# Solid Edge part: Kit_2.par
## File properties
Author: ahadarics
Last saved by: psaghy
Revision: 78
Sűrűség: 0,000 kg/m^3
Pontosság: 0,990
Username: ahadarics
Dokumentum tartalom típus: 0
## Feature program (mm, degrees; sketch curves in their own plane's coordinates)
base feature "unnamed BaseFeature 1"
sketch for "Furat_2" plane through (0, -3.875, 7) normal (0, 0, 1) x-axis (0, 1, 0)
  hole centre (-0.625, 0) bore radius 2.067
hole "Furat_2" nominal diameter 5 finite  ThreadDepth = 4.5 mm
sketch for "Kihúzás_1" #1 plane through (0, 12.5, 0) normal (0, 1, 0) x-axis (0, 0, -1)
  arc centre (0, 0) radius 6 from (4.4721, -4) to (-4.4721, -4) cw
  line (-4.4721, -4) -> (4.4721, -4)
sketch for "Kihúzás_1" #2 plane through (0, 12.5, 0) normal (0, 1, 0) x-axis (0, 0, -1)
  line (-4.4721, 4) -> (4.4721, 4)
extrude "Kihúzás_1" add finite 8.92 along -normal
thread "unnamed Thread 1"
chamfer "Letörés_1" setback 1
sketch for "Kivágás_1" #1 plane through (0, 12.5, 0) normal (0, 1, 0) x-axis (0, 0, -1)
  line (-4.4721, -4) -> (4.4721, -4)
  arc centre (0, 0) radius 6 from (4.4721, -4) to (-4.4721, -4) cw
sketch for "Kivágás_1" #2 plane through (0, 12.5, 0) normal (0, 1, 0) x-axis (0, 0, -1)
  line (-4.4721, 4) -> (4.4721, 4)
extrude "Kivágás_1" cut finite 9.92 along -normal
chamfer "Letörés_2" setback 0.5
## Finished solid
Body 1: solid body, 32 faces, 71 edges, 40 vertices.
  Faces by surface: plane 13, cylinder 11, cone 8
  Edges by curve: line 32, circle 31, intersection 4, spline 4
Bounding box of the edges (mm): 16.000 x 22.250 x 15.000, from (-8, -9.75, -8) to (8, 12.5, 7).
Cylindrical faces by radius (mm): R2 x1, R2.06 x1, R2.067 x1, R5 x2, R5.6 x1, R6 x4, R8 x1
Conical faces (half-angle, radius in mm at the cone's reference point): 45 deg R2.1 x2, 45 deg R2.567 x1, 45 deg R6 x2, 59 deg R1.0335 x1, 60 deg R5.5 x2
Planar faces by outward normal: +x 1, +y 7, +z 2, -x 1, -y 2
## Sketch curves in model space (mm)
arc centre (0, 12.5, 0) radius 6 from (4, 12.5, -4.4721) through (5.9975, 12.5, 0.174) to (4, 12.5, 4.4721)
line (4, 12.5, 4.4721) -> (4, 12.5, -4.4721)
arc centre (0, 12.5, 0) radius 6 from (-4, 12.5, 4.4721) through (-5.9975, 12.5, -0.174) to (-4, 12.5, -4.4721)
line (-4, 12.5, 4.4721) -> (-4, 12.5, -4.4721)
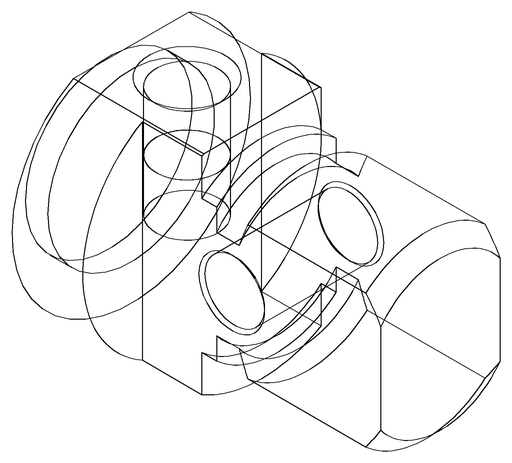
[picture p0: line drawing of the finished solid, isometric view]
